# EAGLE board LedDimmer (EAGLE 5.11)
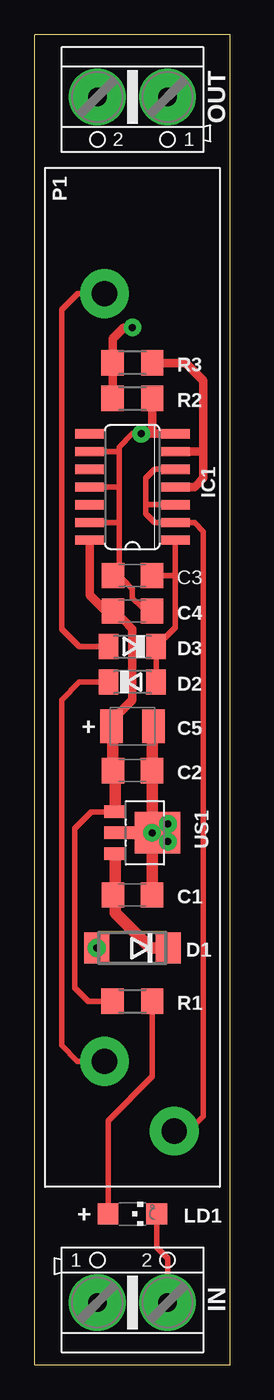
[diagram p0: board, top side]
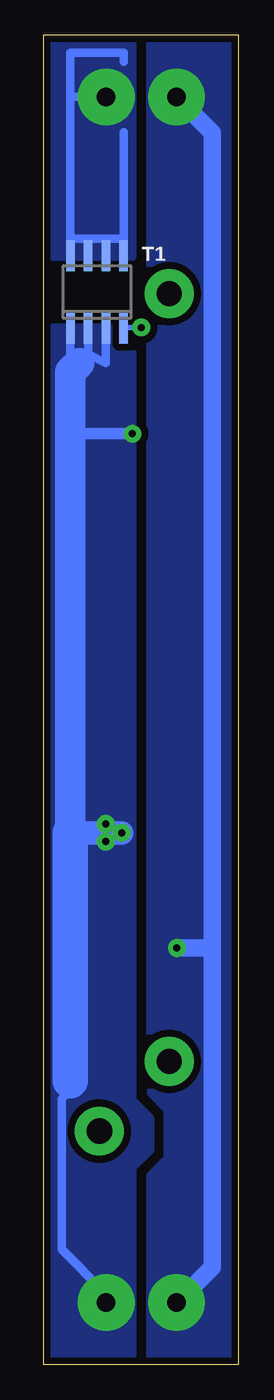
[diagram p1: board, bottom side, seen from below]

Size 13.97 x 95.25 mm. Coordinates in mm from the lower left corner, seen from the top.
Outline: 0,0 13.97,0 13.97,95.25 0,95.25 0,0
Copper layers (1*16): Top 0.035mm / dielectric 1.5mm / Bottom 0.035mm
Design rules "default *": minimum track width 16mil, minimum drill 24mil, track to track 8mil, track to pad 8mil, pad to pad 8mil, via to via 8mil, smd to smd 8mil, copper to edge 10mil, drill to drill 20mil, minimum pad ring 10mil, minimum via ring 8mil, stop-mask expansion 4mil, vias tented up to drill 0mil, thermal gap 10mil

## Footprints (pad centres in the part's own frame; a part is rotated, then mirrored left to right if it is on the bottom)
C1206 = smd 1.6 x 1.8: 1 -1.4,0; 2 1.4,0
SMC_B = smd 1.6 x 2.4: + -1.5,0; - 1.5,0
DO214AA = smd 1.8 x 2.2: A 2.55,0; C -2.55,0
SOD80C = smd 1.4 x 1.8: A 1.7,0; C -1.7,0
SO14 = smd 0.66 x 2.032: 1 -3.81,-3.073; 2 -2.54,-3.073; 3 -1.27,-3.073; 4 0,-3.073; 5 1.27,-3.073; 6 2.54,-3.073; 7 3.81,-3.073; 8 3.81,3.073; 9 2.54,3.073; 10 1.27,3.073; 11 0,3.073; 12 -1.27,3.073; 13 -2.54,3.073; 14 -3.81,3.073
AK500/2 = drill 1.321 pad 4.064 round: 1 -2.515,0; 2 2.515,0
CHIPLED_1206 = smd 1.5 x 1.5: A 0,-1.75; C 0,1.75
TELPOD_LONG_X1 = drill 1.8 pad 3.5 round: 1 2,64; 2 -3,69; 3 2,9
R1206 = smd 1.6 x 1.803: 1 -1.422,0; 2 1.422,0
SO-08 = smd 0.6 x 2.2: 1 -1.905,-2.6; 2 -0.635,-2.6; 3 0.635,-2.6; 4 1.905,-2.6; 5 1.905,2.6; 6 0.635,2.6; 7 -0.635,2.6; 8 -1.905,2.6
SOT89 = smd 0.9 x 1.55: 1 -1.5,-1.875; 3 1.5,-1.875 | smd 0.9 x 2.5: 2 0,-1.4 | smd 3 x 3.25: 4 0,1.15

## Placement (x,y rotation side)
C1  [C1206]  6.99,33.66 0 top
C2  [C1206]  6.99,42.55 0 top
C3  [C1206]  6.99,56.52 180 top
C4  [C1206]  6.99,53.98 0 top
C5  [SMC_B]  6.99,45.72 0 top
D1  [DO214AA]  6.99,29.84 180 top
D2  [SOD80C]  6.99,48.9 0 top
D3  [SOD80C]  6.99,51.44 180 top
IC1  [SO14]  6.99,62.87 90 top
IN  [AK500/2]  6.99,4.45 0 top
LD1  [CHIPLED_1206]  6.99,10.79 270 top
OUT  [AK500/2]  6.99,90.81 180 top
P1  [TELPOD_LONG_X1]  6.99,85.72 180 top
R1  [R1206]  6.99,26.04 180 top
R2  [R1206]  6.99,69.22 180 top
R3  [R1206]  6.99,71.75 0 top
T1  [SO-08]  10.16,76.83 0 bottom
US1  [SOT89]  7.62,38.1 270 top

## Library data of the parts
C1 C2 = resistor
C3-C5 R1-R3 = rcl
D1-D3 = diode
IC1 = 74xx-eu
IN OUT = con-ptr500; OC_FARNELL: unknown; OC_NEWARK: unknown
LD1 = led
P1 = pot
T1 = transistor-power
US1 = v-reg

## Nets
DREN: OUT.1 T1.5 T1.6 T1.7 T1.8
GND: C1.2 C2.2 C3.2 C4.2 C5.- IC1.7 IC1.9 IC1.11 IC1.13 IN.2 LD1.C R2.1 T1.1 T1.2 T1.3 US1.2 US1.4
N$1: LD1.A R1.1
N$2: C1.1 D1.C US1.3
N$4: IC1.2 IC1.3 IC1.5 P1.2
N$5: IC1.4 IC1.6 R3.2
N$7: D2.C P1.1
N$8: D3.A P1.3
N$9: C3.1 D2.A D3.C IC1.1
N$12: R2.2 R3.1 T1.4
V+: D1.A IN.1 OUT.2
VCC: C2.1 C4.1 C5.+ IC1.14 R1.2 US1.1

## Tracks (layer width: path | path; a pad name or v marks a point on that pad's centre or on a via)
DREN
  Bottom 0.61: 8.26,80.64 T1.5 | 9.53,80.64 8.26,80.64 | T1.6 9.53,80.64 | 10.79,80.64 T1.7 | 9.53,80.64 10.79,80.64 | 12.06,80.64 T1.8 | 10.79,80.64 12.06,80.64 | 12.06,80.64 12.06,90.81 | 12.06,90.81 12.06,93.98 8.26,93.98 8.26,93.34 | 8.26,80.64 8.26,88.27 | 12.06,90.81 OUT.1
  pour Bottom (isolate 0.508, no thermals): 7.62,79.38 13.34,79.38 13.34,94.61 7.62,94.61
GND  (via drill 0.5 pad 1.27)
  Top 0.406: 6.03,60.33 IC1.13 | 6.03,62.87 6.03,60.33 | 6.03,65.41 6.03,62.87 | 6.03,65.41 IC1.9 | 6.03,62.87 IC1.11 | 8.38,45.62 C5.- | LD1.C 8.73,8.41 9.53,7.62 9.53,5.11 IN.2 | v8.38,38.1 US1.4 | C3.2 5.71,56.65 | C3.2 5.58,56.33 5.71,56.2 6.35,56.2 6.99,55.56 6.99,54.93 7.62,54.29 8.26,54.29 C4.2 | 6.03,60.33 6.03,56.96 C3.2 | 6.03,65.41 6.03,65.72 6.99,66.67 v7.62,66.67 | 8.26,66.67 8.41,66.83
  Top 0.61: v8.38,38.1 US1.2 | v7.62,66.67 8.26,66.67 IC1.7 | 8.41,66.83 R2.1
  Top 0.813: 8.38,45.62 C2.2 v8.38,38.1 C1.2
  Bottom 0.406: 11.43,71.75 11.43,72.39 | v9.53,38.73 9.53,38.1 v9.53,37.47
  Bottom 0.61: T1.3 9.53,71.75 10.79,72.39 | 10.79,72.39 T1.2 | T1.1 12.06,72.39 11.43,72.39 10.79,72.39 | IN.2 9.53,5.08 12.7,8.26 12.7,19.05 12.06,19.68 12.06,20.32
  Bottom 0.813: 12.06,66.67 v7.62,66.67
  Bottom 1.676: 12.06,38.1 9.53,38.1 v8.38,38.1
  Bottom 2.184: 12.06,38.1 12.06,66.67 12.06,71.12 11.43,71.75
  Bottom 2.54: 12.06,20.32 12.06,38.1
  pour Bottom (isolate 0.508, no thermals): 7.62,0.64 13.34,0.64 13.34,20.32 7.62,20.32 7.62,18.89 6.35,17.62 6.35,15.4 7.62,14.13
  pour Bottom (isolate 0.508, no thermals): 7.62,74.3 13.34,74.3 13.34,20.32 7.62,20.32
N$1
  Top 0.406: LD1.A 5.24,17.46 8.41,20.63 R1.1
N$2
  Top 0.406: 5.75,33.66 C1.1
  Top 0.813: US1.3 5.75,33.66 5.75,32.35 8.26,29.84 D1.C
N$4
  Top 0.406: 7.94,61.59 7.94,60.96 8.57,60.33 IC1.2 11.43,60.33 12.06,59.69 12.06,17.78 11.01,16.73 P1.2 | 7.94,61.59 7.94,63.5 8.57,64.14 IC1.5 | 7.94,61.59 IC1.3
N$5
  Top 0.61: IC1.4 11.43,62.87 12.06,63.5 12.06,65.41 | 12.06,65.41 IC1.6 | 12.06,65.41 12.06,70.48 10.79,71.75 R3.2
N$7
  Top 0.406: D2.C 3.17,48.9 1.91,47.62 1.91,22.86 3.04,21.73 P1.1
N$8
  Top 0.406: D3.A 3.17,51.44 1.91,52.7 1.91,75.56 3.06,76.72 P1.3
N$9
  Top 0.406: D2.A D3.C 10.06,52.81 10.06,56.52 | 10.06,56.52 IC1.1 | 10.06,56.52 C3.1
N$12  (via drill 0.5 pad 1.27)
  Top 0.61: R2.2 R3.1 5.56,73.51 6.35,74.3 v6.99,74.3
  Bottom 0.406: v6.99,74.3 8.2,74.3 T1.4
V+  (via drill 0.5 pad 1.27)
  Bottom 1.27: IN.1 4.45,4.45 1.91,6.99 1.91,29.84 | 1.91,29.84 1.91,88.24 OUT.2 | 1.91,29.84 v4.43,29.84
  pour Bottom (isolate 0.508, no thermals): 6.35,0.64 0.64,0.64 0.64,94.61 6.35,94.61 6.35,19.53 5.08,18.26 5.08,14.76 6.35,13.49
VCC
  Top 0.406: 5.75,42.55 C2.1 | 5.58,45.72 C5.+ | R1.2 3.81,26.04 2.86,26.99 2.86,38.42 4.04,39.6 US1.1
  Top 0.61: IC1.14 3.91,55.14 5.08,53.98 C4.1 6.35,53.34 6.99,52.7 6.99,47.62 5.49,46.12 C5.+
  Top 0.813: US1.1 5.75,42.55 | C2.1 5.58,45.72

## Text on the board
tNames: + | +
